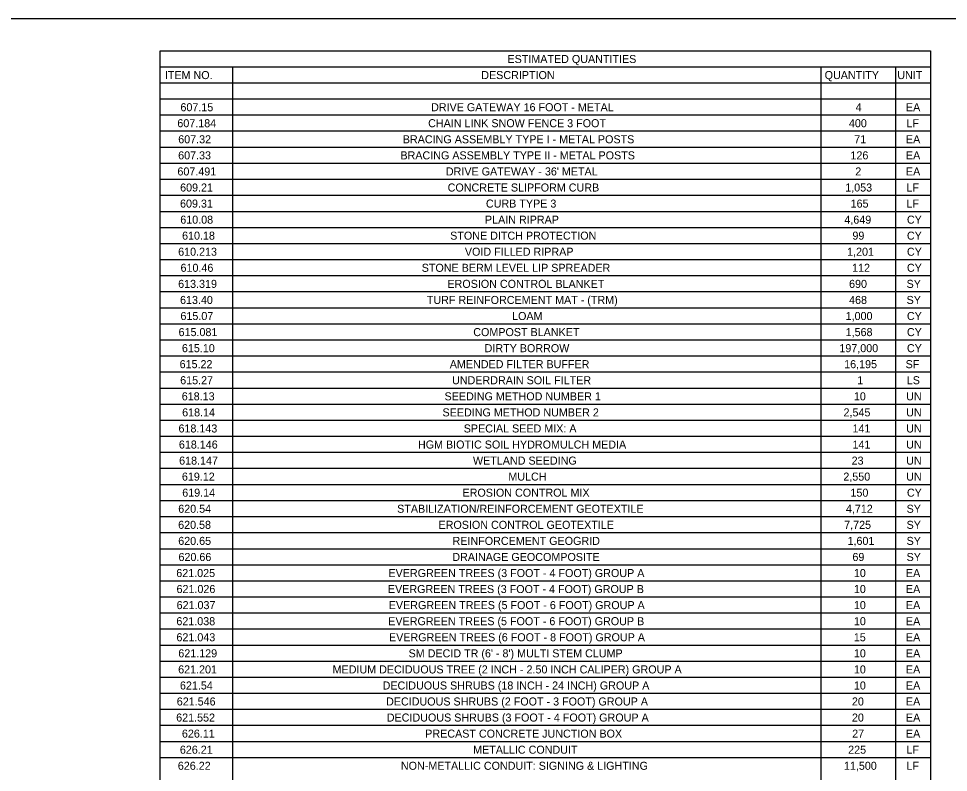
# Model space of a CAD drawing. Extents: x -18.7 to 5.6, y -2.7 to 5.1.
# Drawn here: x -15.505 to -14.366, y 3.09 to 4.014 of the extents above; entities that cross this region are included whole.
import ezdxf

# ---------------------------------------------------------------- set-up
doc = ezdxf.new("R2010")
doc.units = 0
doc.layers.add('ANNOTATION', color=7, linetype='Continuous')
doc.layers.add('BORDER', color=7, linetype='Continuous')

msp = doc.modelspace()

# ---------------------------------------------------------------- linework, layer by layer
at = {"layer": 'ANNOTATION'}
msp.add_lwpolyline([(-17.663, 4.0141), (-13.3075, 4.0141), (-13.3075, 2.1719), (-17.663, 2.1719)], close=True, dxfattribs=at)
at = {"layer": 'BORDER'}
for p, q in [((-15.3321, 3.9551), (-14.3878, 3.9551)), ((-15.2435, 3.9551), (-15.2435, 2.2424)), ((-14.5222, 3.9551), (-14.5222, 2.2424)), ((-14.4308, 3.9551), (-14.4308, 2.2424)), ((-15.3321, 3.9354), (-14.3878, 3.9354)), ((-15.3321, 3.9157), (-14.3878, 3.9157)), ((-15.3321, 3.896), (-14.3878, 3.896)), ((-15.3321, 3.8764), (-14.3878, 3.8764)), ((-15.3321, 3.8567), (-14.3878, 3.8567)), ((-15.3321, 3.837), (-14.3878, 3.837)), ((-15.3321, 3.8173), (-14.3878, 3.8173)), ((-15.3321, 3.7976), (-14.3878, 3.7976)), ((-15.3321, 3.7779), (-14.3878, 3.7779)), ((-15.3321, 3.7582), (-14.3878, 3.7582)), ((-15.3321, 3.7386), (-14.3878, 3.7386)), ((-15.3321, 3.7189), (-14.3878, 3.7189)), ((-15.3321, 3.6992), (-14.3878, 3.6992)), ((-15.3321, 3.6795), (-14.3878, 3.6795)), ((-15.3321, 3.6598), (-14.3878, 3.6598)), ((-15.3321, 3.6401), (-14.3878, 3.6401)), ((-15.3321, 3.6204), (-14.3878, 3.6204)), ((-15.3321, 3.6008), (-14.3878, 3.6008)), ((-15.3321, 3.5811), (-14.3878, 3.5811)), ((-15.3321, 3.5614), (-14.3878, 3.5614)), ((-15.3321, 3.5417), (-14.3878, 3.5417)), ((-15.3321, 3.522), (-14.3878, 3.522)), ((-15.3321, 3.5023), (-14.3878, 3.5023)), ((-15.3321, 3.4826), (-14.3878, 3.4826)), ((-15.3321, 3.463), (-14.3878, 3.463)), ((-15.3321, 3.4433), (-14.3878, 3.4433)), ((-15.3321, 3.4236), (-14.3878, 3.4236)), ((-15.3321, 3.4039), (-14.3878, 3.4039)), ((-15.3321, 3.3842), (-14.3878, 3.3842)), ((-15.3321, 3.3645), (-14.3878, 3.3645)), ((-15.3321, 3.3448), (-14.3878, 3.3448)), ((-15.3321, 3.3251), (-14.3878, 3.3251)), ((-15.3321, 3.3055), (-14.3878, 3.3055)), ((-15.3321, 3.2858), (-14.3878, 3.2858)), ((-15.3321, 3.2661), (-14.3878, 3.2661)), ((-15.3321, 3.2464), (-14.3878, 3.2464)), ((-15.3321, 3.2267), (-14.3878, 3.2267)), ((-15.3321, 3.207), (-14.3878, 3.207)), ((-15.3321, 3.1873), (-14.3878, 3.1873)), ((-15.3321, 3.1677), (-14.3878, 3.1677)), ((-15.3321, 3.148), (-14.3878, 3.148)), ((-15.3321, 3.1283), (-14.3878, 3.1283)), ((-15.3321, 3.1086), (-14.3878, 3.1086))]:
    msp.add_line(p, q, dxfattribs=at)
msp.add_lwpolyline([(-15.3321, 3.9748), (-14.3878, 3.9748), (-14.3878, 2.2424), (-15.3321, 2.2424)], close=True, dxfattribs=at)

# ---------------------------------------------------------------- texts
at = {"layer": 'ANNOTATION'}
for s, height, p in [('607.15', 0.00984, (-15.3071, 3.9006)), ('DRIVE GATEWAY 16 FOOT - METAL', 0.009843, (-14.9999, 3.9006)), ('4', 0.00984, (-14.4796, 3.9006)), ('EA', 0.00984, (-14.4179, 3.9006)), ('607.184', 0.00984, (-15.3109, 3.881)), ('CHAIN LINK SNOW FENCE 3 FOOT', 0.009843, (-15.0035, 3.881)), ('400', 0.00984, (-14.4878, 3.881)), ('LF', 0.00984, (-14.4173, 3.881)), ('607.32', 0.00984, (-15.3098, 3.8613)), ('BRACING ASSEMBLY TYPE I - METAL POSTS', 0.009843, (-15.0346, 3.8613)), ('71', 0.00984, (-14.4813, 3.8613)), ('EA', 0.00984, (-14.4179, 3.8613)), ('607.33', 0.00984, (-15.3099, 3.8416)), ('BRACING ASSEMBLY TYPE II - METAL POSTS', 0.009843, (-15.0375, 3.8416)), ('126', 0.00984, (-14.4859, 3.8416)), ('EA', 0.00984, (-14.4179, 3.8416)), ('607.491', 0.00984, (-15.3108, 3.8219)), ("DRIVE GATEWAY - 36' METAL", 0.009843, (-14.9818, 3.8219)), ('2', 0.00984, (-14.48, 3.8219)), ('EA', 0.00984, (-14.4179, 3.8219)), ('609.21', 0.00984, (-15.3075, 3.8022)), ('CONCRETE SLIPFORM CURB', 0.009843, (-14.9796, 3.8022)), ('1,053', 0.00984, (-14.4923, 3.8022)), ('LF', 0.00984, (-14.4173, 3.8022)), ('609.31', 0.00984, (-15.3076, 3.7825)), ('CURB TYPE 3', 0.009843, (-14.9327, 3.7825)), ('165', 0.00984, (-14.4857, 3.7825)), ('LF', 0.00984, (-14.4173, 3.7825)), ('610.08', 0.00984, (-15.3073, 3.7628)), ('PLAIN RIPRAP', 0.009843, (-14.9339, 3.7628)), ('4,649', 0.00984, (-14.4934, 3.7628)), ('CY', 0.00984, (-14.4167, 3.7628)), ('610.18', 0.00984, (-15.3051, 3.7432)), ('STONE DITCH PROTECTION', 0.009843, (-14.9765, 3.7432)), ('99', 0.00984, (-14.4835, 3.7432)), ('CY', 0.00984, (-14.4167, 3.7432)), ('610.213', 0.00984, (-15.3099, 3.7235)), ('VOID FILLED RIPRAP', 0.009843, (-14.9585, 3.7235)), ('1,201', 0.00984, (-14.49, 3.7235)), ('CY', 0.00984, (-14.4167, 3.7235)), ('610.46', 0.00984, (-15.307, 3.7038)), ('STONE BERM LEVEL LIP SPREADER', 0.009843, (-15.0114, 3.7038)), ('112', 0.00984, (-14.4839, 3.7038)), ('CY', 0.00984, (-14.4167, 3.7038)), ('613.319', 0.00984, (-15.3099, 3.6841)), ('EROSION CONTROL BLANKET', 0.009843, (-14.9799, 3.6841)), ('690', 0.00984, (-14.4876, 3.6841)), ('SY', 0.00984, (-14.4171, 3.6841)), ('613.40', 0.00984, (-15.3076, 3.6644)), ('TURF REINFORCEMENT MAT - (TRM)', 0.009843, (-15.0051, 3.6644)), ('468', 0.00984, (-14.4876, 3.6644)), ('SY', 0.00984, (-14.4171, 3.6644)), ('615.07', 0.00984, (-15.3071, 3.6447)), ('LOAM', 0.00984, (-14.9006, 3.6447)), ('1,000', 0.00984, (-14.4918, 3.6447)), ('CY', 0.00984, (-14.4167, 3.6447)), ('615.081', 0.00984, (-15.3094, 3.625)), ('COMPOST BLANKET', 0.009843, (-14.9482, 3.625)), ('1,568', 0.00984, (-14.4918, 3.625)), ('CY', 0.00984, (-14.4167, 3.625)), ('615.10', 0.00984, (-15.3053, 3.6053)), ('DIRTY BORROW', 0.009843, (-14.9343, 3.6053)), ('197,000', 0.00984, (-14.4995, 3.6053)), ('CY', 0.00984, (-14.4167, 3.6053)), ('615.22', 0.00984, (-15.3081, 3.5857)), ('AMENDED FILTER BUFFER ', 0.009843, (-14.977, 3.5857)), ('16,195', 0.00984, (-14.4936, 3.5857)), ('SF', 0.00984, (-14.4183, 3.5857)), ('615.27', 0.00984, (-15.3074, 3.566)), ('UNDERDRAIN SOIL FILTER', 0.009843, (-14.9742, 3.566)), ('1', 0.00984, (-14.4776, 3.566)), ('LS', 0.00984, (-14.4169, 3.566)), ('618.13', 0.00984, (-15.3055, 3.5463)), ('SEEDING METHOD NUMBER 1', 0.009843, (-14.9834, 3.5463)), ('10', 0.00984, (-14.4817, 3.5463)), ('UN', 0.00984, (-14.4176, 3.5463)), ('618.14', 0.00984, (-15.305, 3.5266)), ('SEEDING METHOD NUMBER 2', 0.009843, (-14.9859, 3.5266)), ('2,545', 0.00984, (-14.4944, 3.5266)), ('UN', 0.00984, (-14.4176, 3.5266)), ('618.143', 0.00984, (-15.3095, 3.5069)), ('SPECIAL SEED MIX: A', 0.009843, (-14.9599, 3.5069)), ('141', 0.00984, (-14.4834, 3.5069)), ('UN', 0.00984, (-14.4176, 3.5069)), ('618.146', 0.00984, (-15.309, 3.4872)), ('HGM BIOTIC SOIL HYDROMULCH MEDIA', 0.009843, (-15.016, 3.4872)), ('141', 0.00984, (-14.4834, 3.4872)), ('UN', 0.00984, (-14.4176, 3.4872)), ('618.147', 0.00984, (-15.3087, 3.4675)), ('WETLAND SEEDING', 0.009843, (-14.9486, 3.4675)), ('23', 0.00984, (-14.4845, 3.4675)), ('UN', 0.00984, (-14.4176, 3.4675)), ('619.12', 0.00984, (-15.3053, 3.4479)), ('MULCH', 0.00984, (-14.9052, 3.4479)), ('2,550', 0.00984, (-14.4946, 3.4479)), ('UN', 0.00984, (-14.4176, 3.4479)), ('619.14', 0.00984, (-15.3049, 3.4282)), ('EROSION CONTROL MIX', 0.009843, (-14.9614, 3.4282)), ('150', 0.00984, (-14.4859, 3.4282)), ('CY', 0.00984, (-14.4167, 3.4282)), ('STABILIZATION/REINFORCEMENT GEOTEXTILE', 0.009843, (-15.0415, 3.4085)), ('620.54', 0.00984, (-15.3098, 3.4085)), ('4,712', 0.00984, (-14.4915, 3.4085)), ('SY', 0.00984, (-14.4171, 3.4085)), ('620.58', 0.00984, (-15.3099, 3.3888)), ('EROSION CONTROL GEOTEXTILE', 0.009843, (-14.9908, 3.3888)), ('7,725', 0.00984, (-14.4936, 3.3888)), ('SY', 0.00984, (-14.4171, 3.3888)), ('620.65', 0.00984, (-15.3098, 3.3691)), ('REINFORCEMENT GEOGRID', 0.009843, (-14.9736, 3.3691)), ('1,601', 0.00984, (-14.4895, 3.3691)), ('SY', 0.00984, (-14.4171, 3.3691)), ('620.66', 0.00984, (-15.3095, 3.3494)), ('DRAINAGE GEOCOMPOSITE', 0.009843, (-14.9739, 3.3494)), ('69', 0.00984, (-14.4835, 3.3494)), ('SY', 0.00984, (-14.4171, 3.3494)), ('621.025', 0.00984, (-15.3122, 3.3297)), ('EVERGREEN TREES (3 FOOT - 4 FOOT) GROUP A', 0.009843, (-15.0522, 3.3297)), ('10', 0.00984, (-14.4817, 3.3297)), ('EA', 0.00984, (-14.4179, 3.3297)), ('621.026', 0.00984, (-15.3119, 3.3101)), ('EVERGREEN TREES (3 FOOT - 4 FOOT) GROUP B', 0.009843, (-15.0528, 3.3101)), ('10', 0.00984, (-14.4817, 3.3101)), ('EA', 0.00984, (-14.4179, 3.3101)), ('621.037', 0.00984, (-15.3118, 3.2904)), ('EVERGREEN TREES (5 FOOT - 6 FOOT) GROUP A', 0.009843, (-15.0518, 3.2904)), ('10', 0.00984, (-14.4817, 3.2904)), ('EA', 0.00984, (-14.4179, 3.2904)), ('621.038', 0.00984, (-15.3121, 3.2707)), ('EVERGREEN TREES (5 FOOT - 6 FOOT) GROUP B', 0.009843, (-15.0524, 3.2707)), ('10', 0.00984, (-14.4817, 3.2707)), ('EA', 0.00984, (-14.4179, 3.2707)), ('621.043', 0.00984, (-15.312, 3.251)), ('EVERGREEN TREES (6 FOOT - 8 FOOT) GROUP A', 0.009843, (-15.0515, 3.251)), ('15', 0.00984, (-14.4818, 3.251)), ('EA', 0.00984, (-14.4179, 3.251)), ('621.129', 0.00984, (-15.3097, 3.2313)), ("SM DECID TR (6' - 8') MULTI STEM CLUMP", 0.009843, (-15.0275, 3.2313)), ('10', 0.00984, (-14.4817, 3.2313)), ('EA', 0.00984, (-14.4179, 3.2313)), ('621.201', 0.00984, (-15.3099, 3.2116)), ('MEDIUM DECIDUOUS TREE (2 INCH - 2.50 INCH CALIPER) GROUP A', 0.009843, (-15.1206, 3.2116)), ('10', 0.00984, (-14.4817, 3.2116)), ('EA', 0.00984, (-14.4179, 3.2116)), ('621.54', 0.00984, (-15.3077, 3.1919)), ('DECIDUOUS SHRUBS (18 INCH - 24 INCH) GROUP A', 0.009843, (-15.0593, 3.1919)), ('10', 0.00984, (-14.4817, 3.1919)), ('EA', 0.00984, (-14.4179, 3.1919)), ('621.546', 0.00984, (-15.3116, 3.1723)), ('DECIDUOUS SHRUBS (2 FOOT - 3 FOOT) GROUP A', 0.009843, (-15.0551, 3.1723)), ('20', 0.00984, (-14.4841, 3.1723)), ('EA', 0.00984, (-14.4179, 3.1723)), ('621.552', 0.00984, (-15.3123, 3.1526)), ('DECIDUOUS SHRUBS (3 FOOT - 4 FOOT) GROUP A', 0.009843, (-15.0542, 3.1526)), ('20', 0.00984, (-14.4841, 3.1526)), ('EA', 0.00984, (-14.4179, 3.1526)), ('626.11', 0.00984, (-15.3053, 3.1329)), ('PRECAST CONCRETE JUNCTION BOX', 0.009843, (-15.0071, 3.1329)), ('27', 0.00984, (-14.4838, 3.1329)), ('EA', 0.00984, (-14.4179, 3.1329)), ('626.21', 0.00984, (-15.3078, 3.1132)), ('METALLIC CONDUIT', 0.009843, (-14.9484, 3.1132)), ('225', 0.00984, (-14.4887, 3.1132)), ('LF', 0.00984, (-14.4173, 3.1132)), ('626.22', 0.00984, (-15.3103, 3.0935)), ('NON-METALLIC CONDUIT: SIGNING & LIGHTING', 0.009843, (-15.0369, 3.0935)), ('11,500', 0.00984, (-14.4939, 3.0935)), ('LF', 0.00984, (-14.4173, 3.0935))]:
    msp.add_text(s, height=height, dxfattribs=at).set_placement(p)
at = {"layer": 'BORDER'}
for s, height, p in [('ESTIMATED QUANTITIES', 0.009843, (-14.9063, 3.9597)), ('ITEM NO.', 0.00984, (-15.3262, 3.94)), ('DESCRIPTION', 0.009843, (-14.9384, 3.94)), ('QUANTITY', 0.00984, (-14.5175, 3.94)), ('UNIT', 0.00984, (-14.4285, 3.94))]:
    msp.add_text(s, height=height, dxfattribs=at).set_placement(p)

doc.saveas('drawing.dxf')
